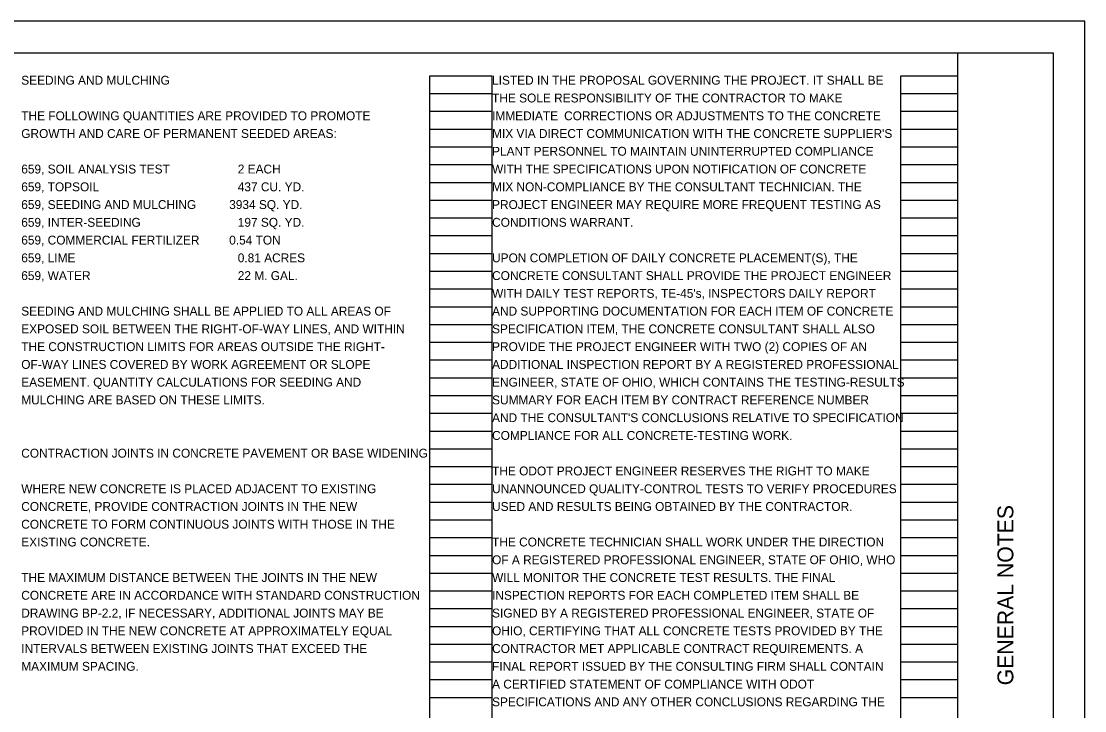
# Model space of a CAD drawing. Extents: x 0 to 76.4, y -34.8 to 22.7.
# Drawn here: x 17.24 to 34, y 11.13 to 22 of the extents above; entities that cross this region are included whole.
import ezdxf

# ---------------------------------------------------------------- set-up
doc = ezdxf.new("R2010")
doc.units = 0
for name, color, linetype in [('SH_Border', 7, 'Continuous'), ('SH_Cut_Line', 7, 'Continuous'), ('SH_Data', 7, 'Continuous'), ('SH_Text', 7, 'Continuous')]:
    doc.layers.add(name, color=color, linetype=linetype)

msp = doc.modelspace()

# ---------------------------------------------------------------- linework, layer by layer
at = {"layer": 'SH_Border'}
msp.add_line((32, 0.5), (32, 21.5), dxfattribs=at)
msp.add_lwpolyline([(1.5, 21.5), (33.5, 21.5), (33.5, 0.5), (1.5, 0.5)], close=True, dxfattribs=at)
at = {"layer": 'SH_Cut_Line'}
msp.add_lwpolyline([(0, 0), (34, 0), (34, 22), (0, 22)], close=True, dxfattribs=at)
at = {"layer": 'SH_Data'}
for p, q in [((23.68, 0.98), (23.68, 21.14)), ((23.68, 21.14), (24.66, 21.14)), ((24.66, 0.98), (24.66, 21.14)), ((31.1, 0.98), (31.1, 21.14)), ((31.1, 21.14), (32, 21.14)), ((32, 0.98), (32, 21.14)), ((23.68, 20.86), (24.66, 20.86)), ((31.1, 20.86), (32, 20.86)), ((23.68, 20.58), (24.66, 20.58)), ((31.1, 20.58), (32, 20.58)), ((23.68, 20.3), (24.66, 20.3)), ((31.1, 20.3), (32, 20.3)), ((23.68, 20.02), (24.66, 20.02)), ((31.1, 20.02), (32, 20.02)), ((23.68, 19.74), (24.66, 19.74)), ((31.1, 19.74), (32, 19.74)), ((23.68, 19.46), (24.66, 19.46)), ((31.1, 19.46), (32, 19.46)), ((23.68, 19.18), (24.66, 19.18)), ((31.1, 19.18), (32, 19.18)), ((23.68, 18.9), (24.66, 18.9)), ((31.1, 18.9), (32, 18.9)), ((23.68, 18.62), (24.66, 18.62)), ((31.1, 18.62), (32, 18.62)), ((23.68, 18.34), (24.66, 18.34)), ((31.1, 18.34), (32, 18.34)), ((23.68, 18.06), (24.66, 18.06)), ((31.1, 18.06), (32, 18.06)), ((23.68, 17.78), (24.66, 17.78)), ((31.1, 17.78), (32, 17.78)), ((23.68, 17.5), (24.66, 17.5)), ((31.1, 17.5), (32, 17.5)), ((23.68, 17.22), (24.66, 17.22)), ((31.1, 17.22), (32, 17.22)), ((23.68, 16.94), (24.66, 16.94)), ((31.1, 16.94), (32, 16.94)), ((23.68, 16.66), (24.66, 16.66)), ((31.1, 16.66), (32, 16.66)), ((23.68, 16.38), (24.66, 16.38)), ((31.1, 16.38), (32, 16.38)), ((23.68, 16.1), (24.66, 16.1)), ((31.1, 16.1), (32, 16.1)), ((23.68, 15.82), (24.66, 15.82)), ((31.1, 15.82), (32, 15.82)), ((23.68, 15.54), (24.66, 15.54)), ((31.1, 15.54), (32, 15.54)), ((23.68, 15.26), (24.66, 15.26)), ((31.1, 15.26), (32, 15.26)), ((23.68, 14.98), (24.66, 14.98)), ((31.1, 14.98), (32, 14.98)), ((23.68, 14.7), (24.66, 14.7)), ((31.1, 14.7), (32, 14.7)), ((23.68, 14.42), (24.66, 14.42)), ((31.1, 14.42), (32, 14.42)), ((23.68, 14.14), (24.66, 14.14)), ((31.1, 14.14), (32, 14.14)), ((23.68, 13.86), (24.66, 13.86)), ((31.1, 13.86), (32, 13.86)), ((23.68, 13.58), (24.66, 13.58)), ((31.1, 13.58), (32, 13.58)), ((23.68, 13.3), (24.66, 13.3)), ((31.1, 13.3), (32, 13.3)), ((23.68, 13.02), (24.66, 13.02)), ((31.1, 13.02), (32, 13.02)), ((23.68, 12.74), (24.66, 12.74)), ((31.1, 12.74), (32, 12.74)), ((23.68, 12.46), (24.66, 12.46)), ((31.1, 12.46), (32, 12.46)), ((23.68, 12.18), (24.66, 12.18)), ((31.1, 12.18), (32, 12.18)), ((23.68, 11.9), (24.66, 11.9)), ((31.1, 11.9), (32, 11.9)), ((23.68, 11.62), (24.66, 11.62)), ((31.1, 11.62), (32, 11.62)), ((23.68, 11.34), (24.66, 11.34)), ((31.1, 11.34), (32, 11.34))]:
    msp.add_line(p, q, dxfattribs=at)

# ---------------------------------------------------------------- texts
msp.add_text('GENERAL NOTES', height=0.25, rotation=90, dxfattribs=at).set_placement((32.875, 11.531))
at = {"layer": 'SH_Text'}
for s, p in [('SEEDING AND MULCHING', (17.24, 21)), ('LISTED IN THE PROPOSAL GOVERNING THE PROJECT. IT SHALL BE', (24.66, 21)), ('THE SOLE RESPONSIBILITY OF THE CONTRACTOR TO MAKE ', (24.66, 20.72)), ('THE FOLLOWING QUANTITIES ARE PROVIDED TO PROMOTE', (17.24, 20.44)), ('IMMEDIATE', (24.66, 20.44)), (' CORRECTIONS OR ADJUSTMENTS TO THE CONCRETE', (25.743, 20.44)), ('GROWTH AND CARE OF PERMANENT SEEDED AREAS:', (17.24, 20.16)), ("MIX VIA DIRECT COMMUNICATION WITH THE CONCRETE SUPPLIER'S", (24.66, 20.16)), ('PLANT PERSONNEL TO MAINTAIN UNINTERRUPTED COMPLIANCE', (24.66, 19.88)), ('659, SOIL ANALYSIS TEST          ', (17.24, 19.6)), (' 2 EACH', (20.6, 19.6)), ('WITH THE SPECIFICATIONS UPON NOTIFICATION OF CONCRETE', (24.66, 19.6)), ('659, TOPSOIL                       ', (17.24, 19.32)), (' 437 CU. YD.', (20.6, 19.32)), ('MIX NON-COMPLIANCE BY THE CONSULTANT TECHNICIAN. THE', (24.66, 19.32)), ('659, SEEDING AND MULCHING          3934 SQ. YD.', (17.24, 19.04)), ('PROJECT ENGINEER MAY REQUIRE MORE FREQUENT TESTING AS', (24.66, 19.04)), ('659, INTER-SEEDING              ', (17.24, 18.76)), (' 197 SQ. YD.', (20.6, 18.76)), ('CONDITIONS WARRANT. ', (24.66, 18.76)), ('659, COMMERCIAL FERTILIZER         0.54 TON', (17.24, 18.48)), ('659, LIME                           ', (17.24, 18.2)), (' 0.81 ACRES', (20.6, 18.2)), ('UPON COMPLETION OF DAILY CONCRETE PLACEMENT(S), THE', (24.66, 18.2)), ('659, WATER                       ', (17.24, 17.92)), (' 22 M. GAL.', (20.6, 17.92)), ('CONCRETE CONSULTANT SHALL PROVIDE THE PROJECT ENGINEER', (24.66, 17.92)), ("WITH DAILY TEST REPORTS, TE-45's, INSPECTORS DAILY REPORT", (24.66, 17.64)), ('SEEDING AND MULCHING SHALL BE APPLIED TO ALL AREAS OF', (17.24, 17.36)), ('AND SUPPORTING DOCUMENTATION FOR EACH ITEM OF CONCRETE', (24.66, 17.36)), ('EXPOSED SOIL BETWEEN THE RIGHT-OF-WAY LINES, AND WITHIN', (17.24, 17.08)), ('SPECIFICATION ITEM, THE CONCRETE CONSULTANT SHALL ALSO', (24.66, 17.08)), ('THE CONSTRUCTION LIMITS FOR AREAS OUTSIDE THE RIGHT-', (17.24, 16.8)), ('PROVIDE THE PROJECT ENGINEER WITH TWO (2) COPIES OF AN', (24.66, 16.8)), ('OF-WAY LINES COVERED BY WORK AGREEMENT OR SLOPE', (17.24, 16.52)), ('ADDITIONAL INSPECTION REPORT BY A REGISTERED PROFESSIONAL', (24.66, 16.52)), ('EASEMENT. QUANTITY CALCULATIONS FOR SEEDING AND', (17.24, 16.24)), ('ENGINEER, STATE OF OHIO, WHICH CONTAINS THE TESTING-RESULTS', (24.66, 16.24)), ('MULCHING ARE BASED ON THESE LIMITS.', (17.24, 15.96)), ('SUMMARY FOR EACH ITEM BY CONTRACT REFERENCE NUMBER', (24.66, 15.96)), ("AND THE CONSULTANT'S CONCLUSIONS RELATIVE TO SPECIFICATION", (24.66, 15.68)), ('COMPLIANCE FOR ALL CONCRETE-TESTING WORK.', (24.66, 15.4)), ('CONTRACTION JOINTS IN CONCRETE PAVEMENT OR BASE WIDENING', (17.24, 15.12)), ('THE ODOT PROJECT ENGINEER RESERVES THE RIGHT TO MAKE', (24.66, 14.84)), ('WHERE NEW CONCRETE IS PLACED ADJACENT TO EXISTING', (17.24, 14.56)), ('UNANNOUNCED QUALITY-CONTROL TESTS TO VERIFY PROCEDURES', (24.66, 14.56)), ('CONCRETE, PROVIDE CONTRACTION JOINTS IN THE NEW', (17.24, 14.28)), ('USED AND RESULTS BEING OBTAINED BY THE CONTRACTOR.', (24.66, 14.28)), ('CONCRETE TO FORM CONTINUOUS JOINTS WITH THOSE IN THE', (17.24, 14)), ('EXISTING CONCRETE.', (17.24, 13.72)), ('THE CONCRETE TECHNICIAN SHALL WORK UNDER THE DIRECTION', (24.66, 13.72)), ('OF A REGISTERED PROFESSIONAL ENGINEER, STATE OF OHIO, WHO', (24.66, 13.44)), ('THE MAXIMUM DISTANCE BETWEEN THE JOINTS IN THE NEW', (17.24, 13.16)), ('WILL MONITOR THE CONCRETE TEST RESULTS. THE FINAL', (24.66, 13.16)), ('CONCRETE ARE IN ACCORDANCE WITH STANDARD CONSTRUCTION', (17.24, 12.88)), ('INSPECTION REPORTS FOR EACH COMPLETED ITEM SHALL BE', (24.66, 12.88)), ('DRAWING BP-2.2, IF NECESSARY, ADDITIONAL JOINTS MAY BE', (17.24, 12.6)), ('SIGNED BY A REGISTERED PROFESSIONAL ENGINEER, STATE OF', (24.66, 12.6)), ('PROVIDED IN THE NEW CONCRETE AT APPROXIMATELY EQUAL', (17.24, 12.32)), ('OHIO, CERTIFYING THAT ALL CONCRETE TESTS PROVIDED BY THE ', (24.66, 12.32)), ('INTERVALS BETWEEN EXISTING JOINTS THAT EXCEED THE', (17.24, 12.04)), ('CONTRACTOR MET APPLICABLE CONTRACT REQUIREMENTS. A', (24.66, 12.04)), ('MAXIMUM SPACING.', (17.24, 11.76)), ('FINAL REPORT ISSUED BY THE CONSULTING FIRM SHALL CONTAIN', (24.66, 11.76)), ('A CERTIFIED STATEMENT OF COMPLIANCE WITH ODOT', (24.66, 11.48)), ('SPECIFICATIONS AND ANY OTHER CONCLUSIONS REGARDING THE', (24.66, 11.2))]:
    msp.add_text(s, height=0.14, dxfattribs=at).set_placement(p)

doc.saveas('drawing.dxf')
